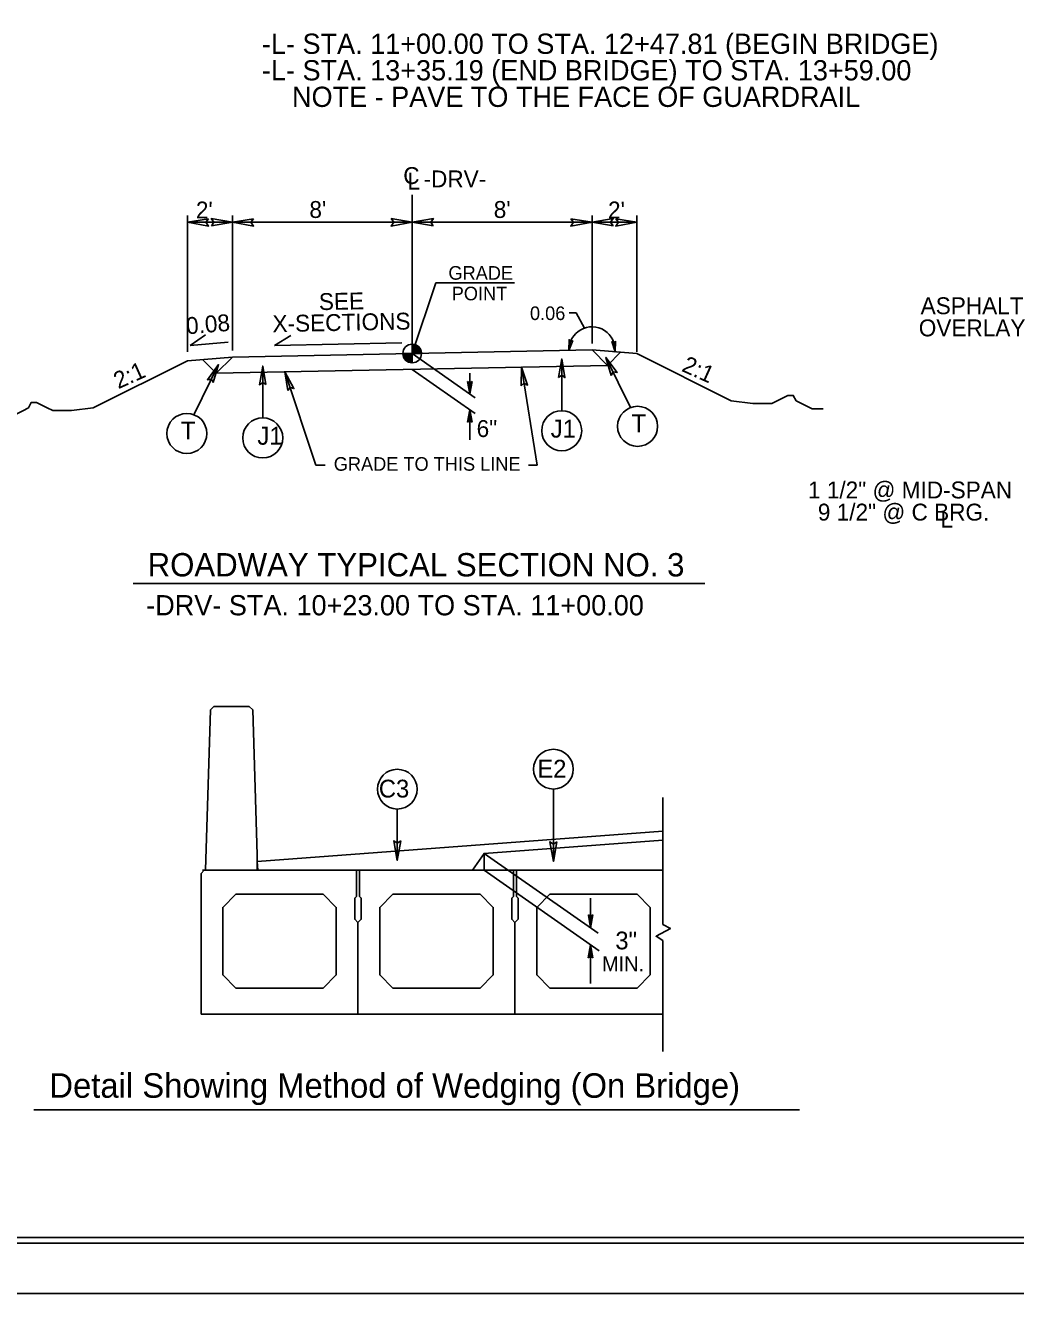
# Model space of a CAD drawing. Extents: x 573711 to 575883, y -54585 to -53485.
# Drawn here: x 574439 to 574880, y -54585 to -54021 of the extents above; entities that cross this region are included whole.
import ezdxf

# ---------------------------------------------------------------- set-up
doc = ezdxf.new("R2010")
doc.units = 0
for name, color, linetype in [('Old_Level_1', 7, 'Continuous'), ('Old_Level_11', 7, 'Continuous'), ('Old_Level_2', 7, 'Continuous'), ('Old_Level_20', 7, 'Continuous'), ('Old_Level_21', 7, 'Continuous'), ('Old_Level_3', 7, 'Continuous'), ('Prop Dimension Text', 7, 'Continuous'), ('Prop Shade Medium', 7, 'Continuous'), ('Sheet Cutting Line CELL', 7, 'Continuous'), ('Sheet Plot Border Inside CELL', 7, 'Continuous'), ('Sheet Plot Border Outside CELL', 7, 'Continuous'), ('Sheet Typical CELL', 7, 'Continuous'), ('Typical Bridge Rail CELL', 7, 'Continuous'), ('Typical Terminator CELL', 7, 'Continuous')]:
    doc.layers.add(name, color=color, linetype=linetype)

msp = doc.modelspace()

# ---------------------------------------------------------------- linework, layer by layer
at = {"layer": 'Old_Level_1'}
for p, q in [((574611.02, -54166.87), (574611.02, -54096.31)), ((574611.02, -54166.87), (574611.02, -54162.72)), ((574511.03, -54170.13), (574531.03, -54168.46)), ((574523.84, -54175.64), (574517.77, -54169.57)), ((574531.03, -54168.46), (574523.84, -54175.64)), ((574531.03, -54168.46), (574691.02, -54165.28)), ((574606.87, -54166.87), (574611.02, -54166.87)), ((574611.01, -54171.02), (574611.02, -54166.87)), ((574611.02, -54166.87), (574611.01, -54171.02)), ((574615.16, -54166.87), (574611.02, -54166.87)), ((574611.02, -54166.87), (574639.11, -54186.54)), ((574691.02, -54165.28), (574697.92, -54172.18)), ((574711.02, -54166.94), (574691.02, -54165.28)), ((574697.92, -54172.18), (574703.76, -54166.34)), ((574752.96, -54187.91), (574711.02, -54166.94)), ((574469.08, -54191.1), (574511.03, -54170.13)), ((574523.84, -54175.64), (574697.92, -54172.18)), ((574611.02, -54173.91), (574639.11, -54193.59)), ((574636.65, -54184.82), (574635.68, -54179.29)), ((574636.65, -54180.01), (574635.68, -54179.29)), ((574636.65, -54184.82), (574635.82, -54179.4)), ((574635.96, -54179.5), (574636.65, -54184.82)), ((574636.65, -54184.82), (574636.09, -54179.6)), ((574636.23, -54179.71), (574636.65, -54184.82)), ((574636.65, -54184.82), (574636.37, -54179.8)), ((574636.51, -54179.91), (574636.65, -54184.82)), ((574636.65, -54175.54), (574636.65, -54184.82)), ((574636.65, -54184.82), (574637.63, -54179.29)), ((574637.63, -54179.29), (574636.65, -54180.01)), ((574637.48, -54179.4), (574636.65, -54184.82)), ((574636.65, -54184.82), (574637.34, -54179.5)), ((574637.21, -54179.6), (574636.65, -54184.82)), ((574636.65, -54184.82), (574637.07, -54179.71)), ((574636.93, -54179.81), (574636.65, -54184.82)), ((574636.65, -54184.82), (574636.79, -54179.91)), ((574636.65, -54180.01), (574636.65, -54184.82)), ((574636.65, -54191.87), (574635.68, -54197.39)), ((574635.82, -54197.28), (574636.65, -54191.87)), ((574636.65, -54191.87), (574635.95, -54197.19)), ((574636.09, -54197.08), (574636.65, -54191.87)), ((574636.65, -54191.87), (574636.23, -54196.98)), ((574636.37, -54196.88), (574636.65, -54191.87)), ((574636.65, -54191.87), (574636.51, -54196.78)), ((574636.65, -54191.87), (574636.65, -54205.21)), ((574636.65, -54191.87), (574637.63, -54197.39)), ((574636.65, -54196.67), (574636.65, -54191.87)), ((574636.79, -54196.78), (574636.65, -54191.87)), ((574636.65, -54191.87), (574636.93, -54196.88)), ((574637.07, -54196.98), (574636.65, -54191.87)), ((574636.65, -54191.87), (574637.2, -54197.08)), ((574637.34, -54197.19), (574636.65, -54191.87)), ((574636.65, -54191.87), (574637.48, -54197.28)), ((574635.68, -54197.39), (574636.65, -54196.67)), ((574636.65, -54196.67), (574637.63, -54197.39)), ((574722.54, -54364.33), (574722.54, -54420.89)), ((574542.03, -54392.76), (574722.54, -54379.32)), ((574643.04, -54389.2), (574722.54, -54383.29)), ((574643.04, -54396.7), (574694.14, -54432.48)), ((574690.42, -54409.12), (574690.42, -54422.38)), ((574690.42, -54422.38), (574689.39, -54416.57)), ((574689.39, -54416.57), (574690.42, -54417.32)), ((574689.53, -54416.68), (574690.42, -54422.38)), ((574690.42, -54422.38), (574689.69, -54416.79)), ((574689.84, -54416.89), (574690.42, -54422.38)), ((574690.42, -54422.38), (574689.98, -54417)), ((574690.13, -54417.11), (574690.42, -54422.38)), ((574690.42, -54422.38), (574690.27, -54417.22)), ((574690.42, -54422.38), (574691.45, -54416.57)), ((574690.42, -54417.32), (574691.45, -54416.57)), ((574690.42, -54422.38), (574691.3, -54416.68)), ((574691.15, -54416.79), (574690.42, -54422.38)), ((574690.42, -54422.38), (574691.01, -54416.89)), ((574690.86, -54417), (574690.42, -54422.38)), ((574690.42, -54422.38), (574690.71, -54417.11)), ((574690.57, -54417.22), (574690.42, -54422.38)), ((574690.42, -54417.32), (574690.42, -54422.38)), ((574722.54, -54427.88), (574722.54, -54477.39)), ((574690.39, -54429.85), (574689.36, -54435.67)), ((574690.39, -54434.91), (574689.36, -54435.67)), ((574690.39, -54429.85), (574689.51, -54435.55)), ((574689.67, -54435.45), (574690.39, -54429.85)), ((574690.39, -54429.85), (574689.81, -54435.34)), ((574689.96, -54435.23), (574690.39, -54429.85)), ((574690.39, -54429.85), (574690.1, -54435.13)), ((574690.25, -54435.02), (574690.39, -54429.85)), ((574690.39, -54429.85), (574690.39, -54447.11)), ((574690.39, -54429.85), (574691.42, -54435.67)), ((574691.27, -54435.55), (574690.39, -54429.85)), ((574690.39, -54429.85), (574691.13, -54435.45)), ((574690.98, -54435.34), (574690.39, -54429.85)), ((574690.39, -54429.85), (574690.83, -54435.23)), ((574690.68, -54435.13), (574690.39, -54429.85)), ((574690.39, -54429.85), (574690.54, -54435.02)), ((574690.39, -54434.91), (574690.39, -54429.85)), ((574691.42, -54435.67), (574690.39, -54434.91))]:
    msp.add_line(p, q, dxfattribs=at)
for points in [[(574611.05, -54162.72), (574611.05, -54162.72), (574611.05, -54166.87)], [(574611.14, -54162.72), (574611.14, -54166.87)], [(574611.22, -54162.73), (574611.22, -54166.87)], [(574611.3, -54162.73), (574611.3, -54166.87)], [(574611.38, -54162.74), (574611.38, -54166.87)], [(574611.47, -54162.75), (574611.47, -54166.87)], [(574611.55, -54162.76), (574611.55, -54166.87)], [(574611.63, -54162.77), (574611.63, -54166.87)], [(574611.72, -54162.78), (574611.72, -54166.87)], [(574611.8, -54162.79), (574611.8, -54166.87)], [(574611.88, -54162.81), (574611.88, -54166.87)], [(574611.97, -54162.83), (574611.97, -54166.87)], [(574612.05, -54162.85), (574612.05, -54166.87)], [(574612.13, -54162.88), (574612.13, -54166.87)], [(574612.21, -54162.9), (574612.21, -54166.87)], [(574612.3, -54162.92), (574612.3, -54166.87)], [(574612.38, -54162.95), (574612.38, -54166.87)], [(574612.46, -54162.98), (574612.46, -54166.87)], [(574612.55, -54163.02), (574612.55, -54166.87)], [(574612.63, -54163.05), (574612.63, -54166.87)], [(574612.71, -54163.09), (574612.71, -54166.87)], [(574612.8, -54163.13), (574612.8, -54166.87)], [(574612.88, -54163.16), (574612.88, -54166.87)], [(574612.96, -54163.21), (574612.96, -54166.87)], [(574613.04, -54163.26), (574613.04, -54166.87)], [(574613.13, -54163.3), (574613.13, -54166.87)], [(574613.21, -54163.35), (574613.21, -54166.87)], [(574613.29, -54163.4), (574613.29, -54166.87)], [(574613.38, -54163.46), (574613.38, -54166.87)], [(574613.46, -54163.52), (574613.46, -54166.87)], [(574613.54, -54163.58), (574613.54, -54166.87)], [(574613.63, -54163.64), (574613.62, -54166.87)], [(574613.71, -54163.72), (574613.71, -54166.87)], [(574613.79, -54163.79), (574613.79, -54166.87)], [(574613.87, -54163.86), (574613.87, -54166.87)], [(574613.96, -54163.95), (574613.96, -54166.87)], [(574614.04, -54164.03), (574614.04, -54166.87)], [(574614.12, -54164.12), (574614.12, -54166.87)], [(574606.89, -54166.87), (574606.89, -54167.32)], [(574606.97, -54166.87), (574606.97, -54167.81)], [(574607.05, -54166.87), (574607.05, -54168.1)], [(574607.14, -54166.87), (574607.14, -54168.35)], [(574607.22, -54166.87), (574607.22, -54168.55)], [(574607.3, -54166.87), (574607.3, -54168.72)], [(574607.38, -54166.87), (574607.38, -54168.88)], [(574607.47, -54166.87), (574607.47, -54169.03)], [(574607.55, -54166.87), (574607.55, -54169.15)], [(574607.63, -54166.87), (574607.63, -54169.27)], [(574607.72, -54166.87), (574607.72, -54169.38)], [(574607.8, -54166.87), (574607.8, -54169.49)], [(574607.88, -54166.87), (574607.88, -54169.59)], [(574607.96, -54166.87), (574607.96, -54169.68)], [(574608.05, -54166.87), (574608.05, -54169.77)], [(574608.13, -54166.87), (574608.13, -54169.86)], [(574608.21, -54166.87), (574608.21, -54169.93)], [(574608.3, -54166.87), (574608.3, -54170)], [(574608.38, -54166.87), (574608.38, -54170.08)], [(574608.46, -54166.87), (574608.46, -54170.14)], [(574608.55, -54166.87), (574608.55, -54170.21)], [(574608.63, -54166.87), (574608.63, -54170.26)], [(574608.71, -54166.87), (574608.71, -54170.32)], [(574608.79, -54166.87), (574608.79, -54170.37)], [(574608.88, -54166.87), (574608.88, -54170.43)], [(574608.96, -54166.87), (574608.96, -54170.47)], [(574609.04, -54166.87), (574609.04, -54170.52)], [(574609.13, -54166.87), (574609.13, -54170.56)], [(574609.21, -54166.87), (574609.21, -54170.6)], [(574609.29, -54166.87), (574609.29, -54170.64)], [(574609.38, -54166.87), (574609.38, -54170.68)], [(574609.46, -54166.87), (574609.46, -54170.71)], [(574609.54, -54166.87), (574609.54, -54170.75)], [(574609.62, -54166.87), (574609.62, -54170.78)], [(574609.71, -54166.87), (574609.71, -54170.8)], [(574609.79, -54166.87), (574609.79, -54170.83)], [(574609.87, -54166.87), (574609.87, -54170.85)], [(574609.96, -54166.87), (574609.96, -54170.88)], [(574610.04, -54166.87), (574610.04, -54170.9)], [(574610.12, -54166.87), (574610.12, -54170.92)], [(574610.2, -54166.87), (574610.2, -54170.93)], [(574610.29, -54166.87), (574610.29, -54170.95)], [(574610.37, -54166.87), (574610.37, -54170.96)], [(574610.45, -54166.87), (574610.45, -54170.98)], [(574610.54, -54166.87), (574610.54, -54170.99)], [(574610.62, -54166.87), (574610.62, -54171)], [(574610.7, -54166.87), (574610.7, -54171.01)], [(574610.79, -54166.87), (574610.79, -54171.01)], [(574610.87, -54166.87), (574610.87, -54171.02)], [(574610.95, -54166.87), (574610.95, -54171.02), (574610.95, -54171.02)], [(574614.21, -54164.22), (574614.21, -54166.87)], [(574614.29, -54164.33), (574614.29, -54166.87)], [(574614.37, -54164.44), (574614.37, -54166.87)], [(574614.45, -54164.56), (574614.45, -54166.87)], [(574614.54, -54164.68), (574614.54, -54166.87)], [(574614.62, -54164.82), (574614.62, -54166.87)], [(574614.7, -54164.97), (574614.7, -54166.87)], [(574614.79, -54165.15), (574614.79, -54166.87)], [(574614.87, -54165.34), (574614.87, -54166.87)], [(574614.95, -54165.57), (574614.95, -54166.87)], [(574615.03, -54165.86), (574615.03, -54166.87)], [(574615.12, -54166.28), (574615.12, -54166.87)], [(574752.96, -54187.91), (574762.57, -54189.11), (574764.97, -54189.11), (574768.58, -54189.11), (574770.99, -54189.11), (574773.39, -54187.91), (574775.79, -54186.71), (574778.2, -54185.5), (574780.6, -54185.5), (574781.81, -54187.91), (574784.21, -54189.11), (574786.61, -54190.32), (574789.02, -54191.51), (574791.42, -54191.51), (574793.82, -54191.51)], [(574469.08, -54191.1), (574459.47, -54192.29), (574457.07, -54192.29), (574453.46, -54192.29), (574451.05, -54192.29), (574448.65, -54191.1), (574446.25, -54189.89), (574443.84, -54188.68), (574441.44, -54188.69), (574440.24, -54191.1), (574437.83, -54192.3), (574435.43, -54193.5), (574433.03, -54194.7), (574430.62, -54194.7)], [(574722.54, -54420.89), (574725.9, -54422.58), (574719.51, -54426.08), (574722.54, -54427.88)]]:
    msp.add_lwpolyline(points, dxfattribs=at)
msp.add_circle((574611.01, -54166.87), 4.15, dxfattribs=at)
for start, end in [(359.9851, 89.9851), (179.9851, 269.9851)]:
    msp.add_arc((574611.01, -54166.87), 4.15, start, end, dxfattribs=at)
at = {"layer": 'Old_Level_11'}
for p, q in [((574511.03, -54166.08), (574511.02, -54105.51)), ((574531.03, -54165.48), (574531.02, -54105.51)), ((574691.02, -54162.41), (574691.02, -54105.53)), ((574711.02, -54166.08), (574711.02, -54105.51)), ((574511.02, -54108.51), (574531.02, -54108.51)), ((574531.02, -54108.51), (574611.02, -54108.51)), ((574691.02, -54108.51), (574611.02, -54108.51)), ((574711.02, -54108.51), (574691.02, -54108.51)), ((574677.54, -54192.3), (574677.54, -54169.27)), ((574708.15, -54190.91), (574697.19, -54168.58)), ((574513.89, -54194.1), (574524.85, -54171.76)), ((574544.51, -54195.49), (574544.51, -54172.46)), ((574486.8, -54269.14), (574741.26, -54269.16)), ((574673.83, -54360.58), (574673.83, -54392.74)), ((574604.4, -54369.46), (574604.4, -54392.3)), ((574637.92, -54396.7), (574643.04, -54389.2)), ((574643.04, -54389.2), (574693.78, -54424.73)), ((574643.04, -54389.2), (574643.04, -54396.7)), ((574783.41, -54503.22), (574442.73, -54503.19))]:
    msp.add_line(p, q, dxfattribs=at)
msp.add_lwpolyline([(574687.67, -54155.55), (574683.93, -54148.84), (574680.84, -54148.84)], dxfattribs=at)
for points in [[(574676.11, -54177.52), (574677.54, -54169.27), (574679, -54177.57), (574677.54, -54176.51)], [(574699.55, -54176.61), (574697.19, -54168.58), (574702.16, -54175.38), (574700.38, -54175.08)], [(574522.49, -54179.8), (574524.85, -54171.76), (574519.88, -54178.56), (574521.66, -54178.26)], [(574545.93, -54180.71), (574544.51, -54172.46), (574543.04, -54180.75), (574544.51, -54179.7)], [(574555.63, -54183.32), (574554.41, -54175.04), (574558.39, -54182.46), (574556.67, -54181.92)], [(574659.5, -54181.32), (574659.59, -54172.94), (574662.36, -54180.9), (574660.74, -54180.09)], [(574542.03, -54392.76), (574722.54, -54379.32), (574722.54, -54383.29), (574643.04, -54389.2), (574637.92, -54396.7), (574542.28, -54396.7)], [(574605.89, -54383.61), (574604.4, -54392.3), (574602.85, -54383.56), (574604.4, -54384.67)], [(574643.04, -54389.2), (574722.54, -54383.29), (574722.54, -54396.7), (574637.92, -54396.7)], [(574675.33, -54384.05), (574673.83, -54392.74), (574672.28, -54384), (574673.83, -54385.11)]]:
    msp.add_lwpolyline(points, close=True, dxfattribs=at)
for centre, radius in [((574677.54, -54201.21), 8.91), ((574711.3, -54199.25), 8.91), ((574510.75, -54202.44), 8.91), ((574544.51, -54204.4), 8.91), ((574673.83, -54351.75), 8.84), ((574604.4, -54360.63), 8.84)]:
    msp.add_circle(centre, radius, dxfattribs=at)
msp.add_arc((574691.02, -54165.28), 10.28, 355.2336, 181.1403, dxfattribs=at)
at = {"layer": 'Old_Level_2'}
for p, q in [((574512.17, -54163.37), (574519.12, -54158.51)), ((574512.17, -54163.37), (574529.19, -54161.88)), ((574549.76, -54163.31), (574557.02, -54158.92)), ((574549.76, -54163.31), (574606.36, -54162.18))]:
    msp.add_line(p, q, dxfattribs=at)
at = {"layer": 'Old_Level_3'}
for p, q in [((574611.02, -54166.87), (574621.55, -54135.49)), ((574621.55, -54135.49), (574656.55, -54135.49)), ((574554.41, -54175.04), (574568.14, -54216.46)), ((574659.59, -54172.94), (574666.6, -54216.46)), ((574568.14, -54216.46), (574572.26, -54216.46)), ((574662.74, -54216.46), (574666.6, -54216.46))]:
    msp.add_line(p, q, dxfattribs=at)
at = {"layer": 'Prop Dimension Text'}
for p, q in [((574586.18, -54396.7), (574517.78, -54396.7)), ((574586.18, -54408.34), (574586.18, -54396.7)), ((574722.54, -54396.7), (574657.48, -54396.7)), ((574657.48, -54396.7), (574657.48, -54408.34)), ((574585.45, -54409.07), (574586.18, -54408.34)), ((574585.45, -54418.53), (574585.45, -54409.07)), ((574657.48, -54408.34), (574658.21, -54409.07)), ((574658.21, -54409.07), (574658.21, -54418.53)), ((574586.9, -54419.98), (574585.45, -54418.53)), ((574586.9, -54460.73), (574586.9, -54419.98)), ((574658.21, -54418.53), (574656.75, -54419.98)), ((574656.75, -54419.98), (574656.75, -54460.73)), ((574517.06, -54460.73), (574586.9, -54460.73)), ((574656.75, -54460.73), (574722.54, -54460.73))]:
    msp.add_line(p, q, dxfattribs=at)
for points in [[(574517.06, -54460.73), (574517.06, -54398.16), (574518.51, -54396.7), (574586.18, -54396.7), (574586.18, -54408.34), (574585.45, -54409.07), (574585.45, -54418.53), (574586.9, -54419.98), (574586.9, -54460.73)], [(574656.75, -54460.73), (574656.75, -54419.98), (574655.3, -54418.53), (574655.3, -54409.07), (574656.03, -54408.34), (574656.03, -54396.7), (574587.63, -54396.7), (574587.63, -54408.34), (574588.36, -54409.07), (574588.36, -54418.53), (574586.9, -54419.98), (574586.9, -54460.73)], [(574571.38, -54449.09), (574577.2, -54443.27), (574577.2, -54413.2), (574571.38, -54407.37), (574532.58, -54407.37), (574526.76, -54413.2), (574526.76, -54443.27), (574532.58, -54449.09)], [(574641.23, -54449.09), (574647.05, -54443.27), (574647.05, -54413.2), (574641.23, -54407.37), (574602.43, -54407.37), (574596.61, -54413.2), (574596.61, -54443.27), (574602.43, -54449.09)], [(574711.08, -54449.09), (574716.9, -54443.27), (574716.9, -54413.2), (574711.08, -54407.37), (574672.27, -54407.37), (574666.45, -54413.2), (574666.45, -54443.27), (574672.27, -54449.09)]]:
    msp.add_lwpolyline(points, close=True, dxfattribs=at)
at = {"layer": 'Prop Shade Medium'}
msp.add_line((574643.04, -54389.2), (574722.54, -54383.29), dxfattribs=at)
msp.add_lwpolyline([(574722.54, -54383.29), (574722.54, -54379.32), (574542.03, -54392.76), (574542.28, -54396.7), (574637.92, -54396.7), (574643.04, -54389.2)], dxfattribs=at)
at = {"layer": 'Sheet Cutting Line CELL'}
msp.add_line((573711.13, -54585.01), (575395.13, -54585.01), dxfattribs=at)
at = {"layer": 'Sheet Plot Border Inside CELL'}
msp.add_lwpolyline([(575390.63, -53507.46), (573724.13, -53507.46), (573724.13, -54562.56), (575390.63, -54562.56)], close=True, dxfattribs=at)
at = {"layer": 'Sheet Plot Border Outside CELL'}
msp.add_lwpolyline([(575395.13, -53485.01), (573711.13, -53485.01), (573711.13, -54585.01), (575395.13, -54585.01)], close=True, dxfattribs=at)
at = {"layer": 'Sheet Typical CELL'}
msp.add_lwpolyline([(575378.13, -53510.01), (573878.13, -53510.01), (573878.13, -54560.01), (575378.13, -54560.01)], close=True, dxfattribs=at)
at = {"layer": 'Typical Bridge Rail CELL'}
for p, q in [((574519, -54396.7), (574521.23, -54325.36)), ((574521.23, -54325.36), (574522.73, -54323.91)), ((574522.73, -54323.91), (574538.55, -54323.91)), ((574540.05, -54325.36), (574538.55, -54323.91)), ((574542.06, -54389.81), (574540.05, -54325.36)), ((574542.06, -54389.81), (574542.06, -54396.7))]:
    msp.add_line(p, q, dxfattribs=at)
at = {"layer": 'Typical Terminator CELL'}
for points in [[(574520.39, -54106.9), (574511.02, -54108.51), (574520.45, -54110.18), (574519.25, -54108.51)], [(574521.65, -54110.13), (574531.02, -54108.51), (574521.6, -54106.85), (574522.79, -54108.51)], [(574540.39, -54106.9), (574531.02, -54108.51), (574540.45, -54110.18), (574539.25, -54108.51)], [(574601.65, -54106.89), (574611.02, -54108.51), (574601.6, -54110.17), (574602.79, -54108.5)], [(574620.39, -54110.12), (574611.02, -54108.51), (574620.45, -54106.84), (574619.25, -54108.51)], [(574681.65, -54106.9), (574691.02, -54108.51), (574681.6, -54110.18), (574682.79, -54108.51)], [(574700.39, -54110.13), (574691.02, -54108.51), (574700.45, -54106.85), (574699.25, -54108.51)], [(574701.65, -54106.9), (574711.02, -54108.51), (574701.6, -54110.18), (574702.79, -54108.51)], [(574690.46, -54108.42), (574691.02, -54108.51), (574690.46, -54108.61), (574690.53, -54108.51)], [(574682.43, -54161.04), (574680.73, -54165.48), (574680.82, -54160.7), (574681.53, -54161.44)], [(574701.51, -54161.38), (574701.26, -54166.13), (574699.88, -54161.55), (574700.77, -54162.05)]]:
    msp.add_lwpolyline(points, close=True, dxfattribs=at)

# ---------------------------------------------------------------- texts
at = {"layer": 'Old_Level_1'}
for s, height, p in [('-L- STA. 11+00.00 TO STA. 12+47.81 (BEGIN BRIDGE)', 9, (574544.17, -54033.59)), ('-L- STA. 13+35.19 (END BRIDGE) TO STA. 13+59.00 ', 9, (574544.17, -54045.39)), ('    NOTE - PAVE TO THE FACE OF GUARDRAIL', 9, (574544.17, -54057.19)), ('1 1/2" @ MID-SPAN', 7.513, (574787.13, -54231.32)), ('9 1/2" @ C BRG.', 7.513, (574791.51, -54241.17)), ('L', 7.51, (574846.06, -54244.29)), ('-DRV- STA. 10+23.00 TO STA. 11+00.00', 9, (574492.67, -54283.33))]:
    msp.add_text(s, height=height, dxfattribs=at).set_placement(p)
for s, rotation, p in [('2:1', 335.7915, (574730.48, -54174.53)), ('2:1', 24.2085, (574480.29, -54182.78)), ('6"', 360, (574639.69, -54204.02))]:
    msp.add_text(s, height=7.513, rotation=rotation, dxfattribs=at).set_placement(p)
at = {"layer": 'Old_Level_11'}
for s, height, rotation, p in [('C', 7.51, 359.9946, (574607.04, -54091.47)), ('L', 7.51, 359.9415, (574608.91, -54094)), ('-DRV-', 7.513, 359.9946, (574616.05, -54092.97)), ("2'", 7.513, 0.0054, (574514.77, -54106.8)), ("8'", 7.513, 0.0054, (574565.28, -54106.58)), ("8'", 7.513, 359.9946, (574647.3, -54106.58)), ("2'", 7.513, 359.9946, (574698.15, -54106.8)), ('ASPHALT', 7.513, 359.9946, (574837.25, -54149.38)), ('OVERLAY', 7.513, 359.9946, (574836.42, -54159.23))]:
    msp.add_text(s, height=height, rotation=rotation, dxfattribs=at).set_placement(p)
at = {"layer": 'Old_Level_20'}
for s, height, p in [('T', 7.98, (574508.05, -54205.11)), ('J1', 7.977, (574672.63, -54204.27)), ('T', 7.98, (574708.61, -54201.93)), ('J1', 7.977, (574542.12, -54207.45))]:
    msp.add_text(s, height=height, dxfattribs=at).set_placement(p)
for s, rotation, p in [('E2', 359.9946, (574666.7, -54355.48)), ('C3', 359.9946, (574596.18, -54364.35)), ('3"', 0.0054, (574701.41, -54431.9))]:
    msp.add_text(s, height=7.908, rotation=rotation, dxfattribs=at).set_placement(p)
at = {"layer": 'Old_Level_21'}
for s, height, rotation, p in [('MIN.', 6.609, 0.0054, (574695.52, -54441.63)), ('Detail Showing Method of Wedging (On Bridge)', 10.9083, 359.9946, (574449.59, -54497.89))]:
    msp.add_text(s, height=height, rotation=rotation, dxfattribs=at).set_placement(p)
at = {"layer": 'Old_Level_3'}
for s, height, rotation, p in [('GRADE', 6.046, 359.9946, (574627.14, -54134.04)), ('SEE', 7.513, 1.1404, (574569.56, -54147.59)), ('POINT', 6.046, 359.9946, (574628.6, -54143.21)), ('0.06', 6.046, 359.9946, (574663.42, -54151.98)), ('0.08', 7.513, 4.7561, (574510.72, -54158.37)), ('X-SECTIONS', 7.513, 1.1404, (574548.93, -54157.4)), ('ROADWAY TYPICAL SECTION NO. 3', 10.3693, 359.9946, (574493.31, -54266))]:
    msp.add_text(s, height=height, rotation=rotation, dxfattribs=at).set_placement(p)
msp.add_text('GRADE TO THIS LINE', height=6.0464, dxfattribs=at).set_placement((574576.12, -54219.01))

doc.saveas('drawing.dxf')
